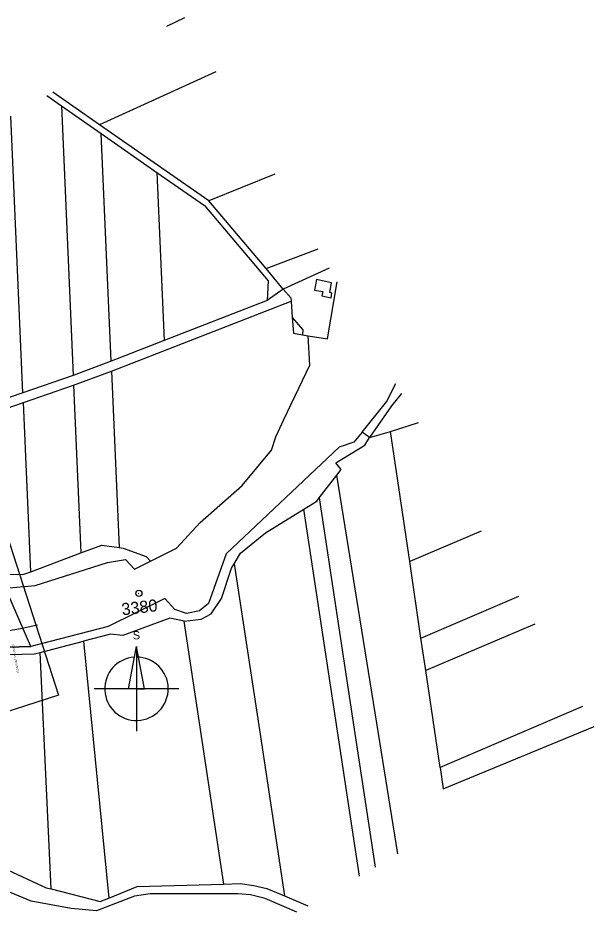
# Model space of a CAD drawing. Extents: x -758836 to -757729, y -1175316 to -1174366.
# Drawn here: x -758098 to -757729, y -1174939 to -1174366 of the extents above; entities that cross this region are included whole.
import ezdxf

# ---------------------------------------------------------------- set-up
doc = ezdxf.new("R2010")
doc.units = 0
for name, color, linetype in [('_NOR-pomocná', 7, 'Continuous'), ('_NOR-popis', 7, 'Continuous'), ('_NOR-severka', 7, 'Continuous'), ('G_Obvod stavby', 7, 'Continuous'), ('Hranice parcel', 7, 'Continuous'), ('Vrstva 1', 7, 'Continuous'), ('Vrstva 63', 7, 'Continuous')]:
    doc.layers.add(name, color=color, linetype=linetype)

# ---------------------------------------------------------------- blocks, each defined once
blk = doc.blocks.new('C015_1')
at = {"layer": 'Vrstva 63'}
blk.add_line((-0.05, 0), (0.05, 0), dxfattribs=at)
blk.add_circle((0, 0), 0.756, dxfattribs=at)
blk = doc.blocks.new('severka')
for p, q in [((-1.2, 0), (0, 6.4)), ((0, 6.4), (0, -6.4)), ((6.4, 0), (-6.4, 0))]:
    blk.add_line(p, q)
blk.add_lwpolyline([(0, 0), (1.2, 0), (0, 6.4)], close=True)
blk.add_arc((0, 0), 4.8, 93.6046, 90)
blk.add_text('S', height=1.25, rotation=0.3139).set_placement((-0.57, 7.48))

msp = doc.modelspace()

# ---------------------------------------------------------------- linework, layer by layer
at = {"layer": '_NOR-pomocná'}
msp.add_lwpolyline([(-758217.71, -1174690.84), (-758117.77, -1174658.65), (-758072.24, -1174800), (-758172.18, -1174832.19)], close=True, dxfattribs=at)
at = {"layer": 'G_Obvod stavby'}
msp.add_lwpolyline([(-758392.72, -1174840.76), (-758391.23, -1174838.56), (-758368.37, -1174821.64), (-758340.31, -1174807.33), (-758320.27, -1174796.89), (-758301, -1174790.21), (-758267.96, -1174782.93), (-758224.96, -1174775.27), (-758184.87, -1174772.83), (-758142.71, -1174770.26), (-758089.84, -1174768.68), (-758106.02, -1174731.44), (-758149.09, -1174725.67), (-758199.62, -1174726.6), (-758225.76, -1174732.36), (-758252.17, -1174738.18), (-758254.97, -1174739.34), (-758266.58, -1174744.16), (-758279.45, -1174749.49), (-758302.42, -1174759.02), (-758331.68, -1174770.24), (-758367.17, -1174799.81), (-758405.64, -1174832.2)], dxfattribs=at)
at = {"layer": 'Hranice parcel'}
for p, q in [((-757991.41, -1174365.74), (-758003.07, -1174371.31)), ((-757971.45, -1174400.31), (-758045.98, -1174434.24)), ((-758045.98, -1174434.24), (-758075.9, -1174413.36)), ((-758070.27, -1174422.16), (-758044.88, -1174439.88)), ((-758070.27, -1174422.16), (-758062.75, -1174595)), ((-758094.97, -1174606.08), (-758102.68, -1174428.83)), ((-757975.97, -1174483.1), (-758045.98, -1174434.24)), ((-758044.88, -1174439.88), (-758009.22, -1174464.77)), ((-758038.54, -1174585.88), (-758044.88, -1174439.88)), ((-758009.22, -1174464.77), (-758004.53, -1174572.62)), ((-757933.57, -1174465.91), (-757975.97, -1174483.1)), ((-757939.23, -1174526.49), (-757975.97, -1174483.1)), ((-757939.23, -1174526.49), (-757905.94, -1174513.77)), ((-757928.16, -1174539.57), (-757939.23, -1174526.49)), ((-757898.72, -1174526.28), (-757928.16, -1174539.57)), ((-757928.16, -1174539.57), (-757938.59, -1174546.91)), ((-758038.26, -1174592.18), (-757923.21, -1174547.33)), ((-757938.59, -1174546.91), (-758004.53, -1174572.62)), ((-757923.21, -1174547.33), (-757922.44, -1174557.9)), ((-758004.53, -1174572.62), (-758038.54, -1174585.88)), ((-757915.78, -1174568.99), (-757912.23, -1174569.67)), ((-758038.54, -1174585.88), (-758062.75, -1174595)), ((-758062.75, -1174595), (-758094.97, -1174606.08)), ((-758062.47, -1174601.25), (-758038.26, -1174592.18)), ((-758038.26, -1174592.18), (-758033.33, -1174705.3)), ((-758094.69, -1174612.33), (-758062.47, -1174601.25)), ((-758062.47, -1174601.25), (-758057.8, -1174708.75)), ((-758094.97, -1174606.08), (-758134.89, -1174619.81)), ((-758134.62, -1174626.06), (-758094.69, -1174612.33)), ((-758089.97, -1174720.79), (-758094.69, -1174612.33)), ((-757859.49, -1174630.9), (-757841.66, -1174625.11)), ((-757872.99, -1174634.73), (-757877.73, -1174631.24)), ((-757872.99, -1174634.73), (-757859.49, -1174630.9)), ((-757847.22, -1174714.28), (-757859.49, -1174630.9)), ((-757905.12, -1174673.47), (-757893.96, -1174658.87)), ((-757801.47, -1174694.72), (-757847.22, -1174714.28)), ((-758089.97, -1174720.79), (-758057.8, -1174708.75)), ((-757840.01, -1174763.29), (-757847.22, -1174714.28)), ((-757966.21, -1174921.06), (-757991.64, -1174752.6)), ((-758083.84, -1174772.54), (-758056.09, -1174765.35)), ((-758056.09, -1174765.35), (-758040.03, -1174930.09)), ((-757836.93, -1174784.23), (-757840.01, -1174763.29)), ((-758076.9, -1174924.17), (-758083.84, -1174772.54)), ((-757827.8, -1174846.29), (-757836.93, -1174784.23)), ((-757927.46, -1174928.58), (-757912.42, -1174934.95))]:
    msp.add_line(p, q, dxfattribs=at)
for points in [[(-758079.72, -1174415.57), (-758070.27, -1174422.16)], [(-758009.22, -1174464.77), (-757978.69, -1174486.08), (-757937.94, -1174534.35), (-757938.59, -1174546.91)], [(-757912.23, -1174569.67), (-757899.81, -1174571.51), (-757893.71, -1174534.95)], [(-757902.94, -1174541.15), (-757903.4, -1174543.94), (-757897.51, -1174545.19), (-757897.01, -1174542.12), (-757898.4, -1174541.89), (-757897.28, -1174535.49), (-757907, -1174533.48), (-757908.27, -1174540.27), (-757902.94, -1174541.15)], [(-757928.16, -1174539.57), (-757923.36, -1174545.24), (-757923.21, -1174547.33)], [(-757922.44, -1174557.9), (-757915.69, -1174565.7), (-757915.78, -1174568.99)], [(-757922.44, -1174557.9), (-757921.71, -1174567.85), (-757915.78, -1174568.99)], [(-758013.3, -1174714.07), (-757996.59, -1174705.74), (-757981.33, -1174689.35), (-757954.6, -1174665.43), (-757935.83, -1174642.88), (-757933.07, -1174634.27), (-757927.84, -1174623.26), (-757911.21, -1174588.28), (-757912.23, -1174569.67)], [(-757877.73, -1174631.24), (-757861.98, -1174611.87), (-757856.12, -1174600.06)], [(-757852.43, -1174606.46), (-757858.86, -1174614.39), (-757872.99, -1174634.73)], [(-757877.73, -1174631.24), (-757883.07, -1174637.8), (-757892.39, -1174640.95), (-757964.85, -1174709.42), (-757976.05, -1174741.17), (-757981.89, -1174745.86), (-757990.29, -1174747.68), (-757997.69, -1174745.08), (-758004.14, -1174738), (-758040.32, -1174755.99), (-758089.84, -1174768.68), (-758142.71, -1174770.26), (-758184.87, -1174772.83)], [(-757893.96, -1174658.87), (-757891.17, -1174655.22), (-757894.62, -1174650.91), (-757875.91, -1174639.6), (-757872.99, -1174634.73)], [(-757854.84, -1174901.71), (-757869.41, -1174811.27), (-757893.96, -1174658.87)], [(-757914.95, -1174680.62), (-757906.69, -1174675.52), (-757905.12, -1174673.47)], [(-757905.12, -1174673.47), (-757883.79, -1174814.77), (-757869.4, -1174910.11)], [(-757959.61, -1174715.65), (-757955.61, -1174708.87), (-757939.6, -1174695.85), (-757914.95, -1174680.62)], [(-757879.43, -1174915.9), (-757894.52, -1174815.94), (-757914.95, -1174680.62)], [(-758057.8, -1174708.75), (-758044.51, -1174703.78), (-758033.33, -1174705.3)], [(-758033.33, -1174705.3), (-758030.68, -1174705.66), (-758016, -1174711.02), (-758013.3, -1174714.07)], [(-758149.09, -1174725.67), (-758106.02, -1174731.44), (-758087.1, -1174729.64), (-758040.84, -1174714.91), (-758029.32, -1174712.86), (-758023.54, -1174719.17), (-758013.3, -1174714.07)], [(-757991.64, -1174752.6), (-757980.81, -1174751.2), (-757974.41, -1174747.76), (-757967.73, -1174737.89), (-757961.29, -1174718.5), (-757959.61, -1174715.65)], [(-757959.61, -1174715.65), (-757943.53, -1174822.15), (-757927.46, -1174928.58)], [(-758130.45, -1174721.94), (-758095.02, -1174722.68), (-758089.97, -1174720.79)], [(-757840.01, -1174763.29), (-757777.35, -1174736.5)], [(-757991.64, -1174752.6), (-758000.82, -1174750.62), (-758030.99, -1174761.66), (-758038.84, -1174760.87), (-758056.09, -1174765.35)], [(-757767.04, -1174754.35), (-757836.93, -1174784.23)], [(-758112.36, -1174774.1), (-758087.64, -1174773.53), (-758083.84, -1174772.54)], [(-757736.5, -1174807.25), (-757827.8, -1174846.29)], [(-757827.8, -1174846.29), (-757825.79, -1174859.97), (-757729.1, -1174820.07)], [(-758114.13, -1174910.8), (-758107.54, -1174910.58), (-758080.03, -1174923.36), (-758076.9, -1174924.17)], [(-757919.47, -1174939.02), (-757939.8, -1174930.25), (-757949.26, -1174927.98), (-757957.21, -1174927.28), (-758013.54, -1174927.25), (-758023.59, -1174928.73), (-758047.8, -1174938.11), (-758063.96, -1174936.81), (-758089.79, -1174931.96), (-758110.46, -1174923.41), (-758137.06, -1174918.45)], [(-758040.03, -1174930.09), (-758021.7, -1174922.52), (-757966.21, -1174921.06)], [(-757966.21, -1174921.06), (-757955.71, -1174920.78), (-757947.16, -1174921.89), (-757938.71, -1174923.81), (-757927.46, -1174928.58)], [(-758076.9, -1174924.17), (-758045.39, -1174932.31), (-758040.03, -1174930.09)]]:
    msp.add_lwpolyline(points, dxfattribs=at)
at = {"layer": 'Vrstva 1'}
msp.add_lwpolyline([(-758275.05, -1174773.29), (-758265.48, -1174771.12), (-758253.61, -1174768.89), (-758243.69, -1174767.43), (-758231.37, -1174766.04), (-758219.36, -1174765.12), (-758206.92, -1174764.5), (-758194.22, -1174764.12), (-758182.01, -1174763.87), (-758170.86, -1174763.68), (-758162.02, -1174763.5), (-758153.19, -1174763.23), (-758152.07, -1174763.19), (-758141.84, -1174762.72), (-758130.4, -1174761.93), (-758120.73, -1174760.98), (-758108.61, -1174759.4), (-758096.47, -1174757.28), (-758085.59, -1174754.92)], dxfattribs=at)

# ---------------------------------------------------------------- block references
at = {"layer": '_NOR-severka', "xscale": 4.232308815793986, "yscale": 4.232308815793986}
msp.add_blockref('severka', (-758022.21, -1174795.85), dxfattribs=at)
at = {"layer": 'Vrstva 63', "xscale": 2.6043784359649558, "yscale": 2.604378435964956, "rotation": 12.24290076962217}
msp.add_blockref('C015_1', (-758020.71, -1174734.63), dxfattribs=at)

# ---------------------------------------------------------------- texts
at = {"layer": '_NOR-popis'}
msp.add_text('KO=KÚ km 106,505 027', height=1.25, rotation=279.64253, dxfattribs=at).set_placement((-758101.88, -1174767.44))
at = {"layer": 'Vrstva 63'}
msp.add_text('3380', height=7.755, rotation=6.96107, dxfattribs=at).set_placement((-758031.32, -1174748.82))

doc.saveas('drawing.dxf')
